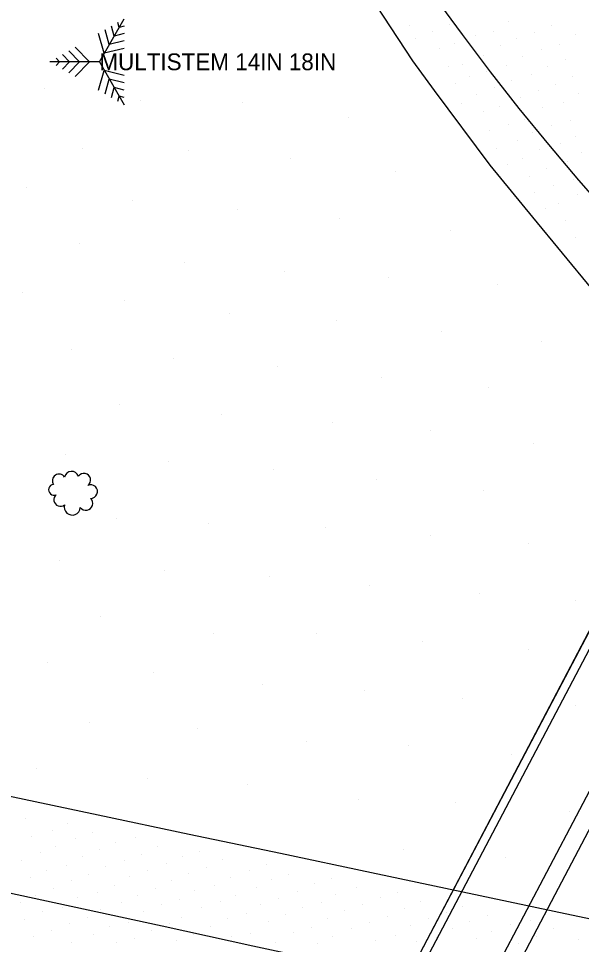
# Model space of a CAD drawing. Extents: x 1732346 to 1733076, y 467730 to 468633.
# Drawn here: x 1732679.1 to 1732739.5, y 468090 to 468189.3 of the extents above; entities that cross this region are included whole.
import ezdxf

# ---------------------------------------------------------------- set-up
doc = ezdxf.new("R2010")
doc.units = 0
for name, color, linetype in [('Default', 7, 'Continuous'), ('S_Bridge_BoxCulvert', 7, 'Continuous'), ('S_Ground_SpotElevation', 7, 'Continuous'), ('S_Railroad_Tracks', 7, 'Continuous'), ('S_Roadway_Edge_Pavement', 7, 'Continuous'), ('S_Roadway_Painted_Lines', 7, 'Continuous'), ('S_Text', 7, 'Continuous'), ('S_Trees_Bush', 7, 'Continuous'), ('S_Trees_Conifer_Pay', 7, 'Continuous'), ('TopoDOT Temp', 7, 'Continuous')]:
    doc.layers.add(name, color=color, linetype=linetype)

# ---------------------------------------------------------------- blocks, each defined once
blk = doc.blocks.new('POINT_DISPLAY')
at = {"layer": 'Default'}
blk.add_line((0, 0), (0, 0), dxfattribs=at)

msp = doc.modelspace()

# ---------------------------------------------------------------- linework, layer by layer
at = {"layer": 'S_Bridge_BoxCulvert'}
for p, q in [((1732639.349, 467931.595), (1732772.729, 468185.159)), ((1732639.356, 467931.621), (1732772.736, 468185.185)), ((1732640.157, 467931.201), (1732773.537, 468184.766)), ((1732646.436, 467927.898), (1732779.815, 468181.463))]:
    msp.add_line(p, q, dxfattribs=at)
at = {"layer": 'S_Railroad_Tracks'}
msp.add_lwpolyline([(1732680.786, 467989.136), (1732685.443, 467997.986), (1732690.1, 468006.835), (1732694.757, 468015.685), (1732699.414, 468024.534), (1732704.07, 468033.384), (1732708.727, 468042.233), (1732713.384, 468051.083), (1732718.041, 468059.932), (1732722.698, 468068.782), (1732727.355, 468077.631), (1732732.012, 468086.481), (1732736.669, 468095.33), (1732741.325, 468104.18), (1732745.982, 468113.029), (1732750.639, 468121.879), (1732755.296, 468130.728), (1732759.953, 468139.578), (1732764.61, 468148.427), (1732769.267, 468157.277), (1732773.924, 468166.126), (1732778.581, 468174.976), (1732783.237, 468183.825), (1732787.789, 468192.475)], dxfattribs=at)
at = {"layer": 'S_Roadway_Edge_Pavement'}
for points in [[(1732823.007, 468089.57), (1732821.659, 468091.736), (1732813.423, 468097.407), (1732807.383, 468101.566), (1732799.356, 468107.529), (1732792.806, 468112.395), (1732784.933, 468118.56), (1732778.351, 468123.714), (1732770.846, 468130.322), (1732766.796, 468133.889), (1732759.562, 468140.794), (1732752.667, 468147.374), (1732745.846, 468154.686), (1732740.622, 468160.287), (1732734.263, 468168.005), (1732729.679, 468173.568), (1732723.729, 468181.605), (1732721.39, 468184.764), (1732715.912, 468193.131)], [(1732677.839, 468105.951), (1732687.624, 468103.887), (1732697.408, 468101.822), (1732707.193, 468099.758), (1732716.978, 468097.693), (1732726.762, 468095.629), (1732736.547, 468093.564), (1732745.022, 468091.776), (1732754.805, 468089.704)]]:
    msp.add_lwpolyline(points, dxfattribs=at)
at = {"layer": 'S_Roadway_Painted_Lines'}
for points in [[(1732742.496, 468168.204), (1732739.21, 468171.965), (1732735.98, 468175.778), (1732732.819, 468179.654), (1732729.734, 468183.579), (1732726.724, 468187.592), (1732723.804, 468191.604)], [(1732674.928, 468096.211), (1732684.719, 468094.102), (1732694.509, 468091.966), (1732704.231, 468089.834), (1732713.923, 468087.737), (1732723.729, 468085.628), (1732733.386, 468083.606), (1732743.244, 468081.582), (1732753.103, 468079.541), (1732762.798, 468077.529), (1732772.584, 468075.483), (1732772.711, 468075.456), (1732782.31, 468073.445), (1732792.144, 468071.365), (1732801.882, 468069.322), (1732811.732, 468067.208), (1732821.504, 468065.09), (1732821.605, 468065.069), (1732831.424, 468062.914)]]:
    msp.add_lwpolyline(points, dxfattribs=at)
at = {"layer": 'S_Trees_Bush'}
for centre, radius, start, end in [((1732683.436, 468139.716), 0.716, 33.64054, 213.59091), ((1732684.789, 468139.951), 0.774, 19.72769, 168.00323), ((1732686.105, 468139.806), 0.714, 304.7168, 145.28321), ((1732682.892, 468138.748), 0.575, 95.18751, 295.46148), ((1732686.832, 468138.562), 0.731, 268.12197, 116.01721), ((1732683.584, 468137.682), 0.705, 129.15555, 309.41051), ((1732686.308, 468137.286), 0.74, 216.98087, 47.49649), ((1732684.858, 468136.897), 0.861, 163.74266, 356.27601)]:
    msp.add_arc(centre, radius, start, end, dxfattribs=at)
at = {"layer": 'S_Trees_Conifer_Pay'}
for p, q in [((1732687.761, 468184.664), (1732690.424, 468189.275)), ((1732689.356, 468187.428), (1732689.055, 468188.484)), ((1732689.89, 468188.352), (1732689.74, 468188.881)), ((1732690.424, 468188.484), (1732689.89, 468188.352)), ((1732688.293, 468185.587), (1732687.686, 468187.693)), ((1732688.827, 468186.508), (1732688.37, 468188.087)), ((1732690.424, 468187.693), (1732689.356, 468187.428)), ((1732690.424, 468186.905), (1732688.827, 468186.508)), ((1732684.566, 468184.664), (1732683.806, 468185.452)), ((1732685.632, 468184.664), (1732684.491, 468185.849)), ((1732686.695, 468184.664), (1732685.175, 468186.246)), ((1732690.424, 468186.111), (1732688.293, 468185.587)), ((1732687.761, 468184.664), (1732682.437, 468184.664)), ((1732683.5, 468184.664), (1732683.122, 468185.058)), ((1732683.122, 468184.27), (1732683.5, 468184.664)), ((1732683.806, 468183.873), (1732684.566, 468184.664)), ((1732684.491, 468183.476), (1732685.632, 468184.664)), ((1732685.175, 468183.082), (1732686.695, 468184.664)), ((1732687.761, 468184.664), (1732690.424, 468180.053)), ((1732687.686, 468181.635), (1732688.293, 468183.741)), ((1732690.424, 468183.214), (1732688.293, 468183.741)), ((1732688.37, 468181.238), (1732688.827, 468182.818)), ((1732690.424, 468182.423), (1732688.827, 468182.818)), ((1732689.055, 468180.841), (1732689.356, 468181.897)), ((1732690.424, 468181.635), (1732689.356, 468181.897)), ((1732689.74, 468180.447), (1732689.89, 468180.976)), ((1732690.424, 468180.841), (1732689.89, 468180.976))]:
    msp.add_line(p, q, dxfattribs=at)
at = {"layer": 'TopoDOT Temp'}
msp.add_line((1732736.669, 468095.33), (1732736.669, 468095.33), dxfattribs=at)

# ---------------------------------------------------------------- block references
at = {"layer": 'S_Ground_SpotElevation'}
for p in [(1732721.005, 468188.524), (1732725.336, 468188.641), (1732731.668, 468189.027), (1732736.313, 468188.604), (1732687.655, 468187.573), (1732723.483, 468187.889), (1732728.143, 468187.444), (1732730.075, 468187.947), (1732734.5, 468187.831), (1732738.874, 468187.545), (1732721.705, 468187.134), (1732725.877, 468186.679), (1732732.555, 468187.164), (1732737.111, 468186.486), (1732698.99, 468185.516), (1732724.248, 468186.076), (1732730.797, 468186.365), (1732735.209, 468185.954), (1732709.393, 468184.816), (1732729.006, 468185.38), (1732733.2, 468185.258), (1732737.769, 468184.901), (1732725.231, 468184.112), (1732726.696, 468184.41), (1732729.331, 468183.667), (1732731.401, 468184.287), (1732735.863, 468184.212), (1732727.428, 468183.053), (1732731.948, 468182.669), (1732734.178, 468183.267), (1732738.503, 468183.062), (1732681.861, 468181.849), (1732725.95, 468182.288), (1732730.162, 468181.944), (1732734.849, 468181.557), (1732736.715, 468182.253), (1732692.18, 468180.569), (1732728.278, 468181.135), (1732732.975, 468180.829), (1732739.144, 468181.242), (1732703.099, 468180.307), (1732726.652, 468180.199), (1732730.704, 468179.842), (1732735.325, 468179.768), (1732737.557, 468180.261), (1732714.539, 468178.694), (1732729.03, 468179.329), (1732733.375, 468178.505), (1732731.707, 468177.891), (1732736.28, 468177.881), (1732738.315, 468178.364), (1732729.599, 468177.317), (1732734.278, 468177.083), (1732738.9, 468176.627), (1732732.659, 468176.275), (1732737.198, 468175.877), (1732685.98, 468175.337), (1732697.342, 468175.12), (1732730.327, 468175.354), (1732735.036, 468175.311), (1732739.458, 468174.884), (1732708.298, 468174.241), (1732731.59, 468173.635), (1732733.118, 468174.294), (1732737.947, 468173.979), (1732719.558, 468172.905), (1732735.766, 468173.224), (1732733.921, 468172.339), (1732738.583, 468172.034), (1732679.976, 468171.195), (1732734.482, 468170.621), (1732736.532, 468171.417), (1732691.358, 468169.833), (1732739.099, 468170.44), (1732702.593, 468168.821), (1732735.595, 468168.885), (1732737.033, 468169.422), (1732713.566, 468167.814), (1732737.783, 468167.637), (1732725.387, 468166.554), (1732738.89, 468165.866), (1732685.677, 468165.208), (1732696.947, 468163.119), (1732707.619, 468162.212), (1732718.734, 468161.474), (1732730.485, 468160.792), (1732679.559, 468159.953), (1732690.487, 468159.041), (1732701.697, 468157.65), (1732713.214, 468156.862), (1732724.449, 468155.732), (1732684.759, 468153.795), (1732735.19, 468154.608), (1732695.671, 468152.857), (1732706.851, 468151.934), (1732718.061, 468150.804), (1732729.562, 468149.681), (1732689.939, 468147.951), (1732700.853, 468146.779), (1732712.827, 468145.953), (1732723.255, 468145.137), (1732734.301, 468143.725), (1732684.157, 468142.581), (1732695.2, 468141.83), (1732706.46, 468140.902), (1732717.533, 468139.86), (1732729.024, 468138.647), (1732689.584, 468135.629), (1732699.515, 468135.124), (1732711.976, 468134.71), (1732723.306, 468133.862), (1732733.758, 468132.99), (1732683.533, 468131.138), (1732694.723, 468130.129), (1732705.979, 468129.461), (1732716.77, 468128.475), (1732728.558, 468127.669), (1732738.816, 468126.837), (1732687.925, 468125.2), (1732700.044, 468123.361), (1732711.035, 468123.369), (1732722.452, 468122.496), (1732733.767, 468121.624), (1732682.154, 468120.172), (1732693.605, 468119.102), (1732705.238, 468117.895), (1732716.23, 468117.203), (1732726.721, 468116.378), (1732738.823, 468115.596), (1732686.749, 468113.754), (1732698.272, 468113.136), (1732709.983, 468111.7), (1732720.948, 468111.267), (1732731.984, 468110.334), (1732681.013, 468108.882), (1732692.96, 468107.793), (1732703.623, 468107.116), (1732715.556, 468105.503), (1732725.973, 468105.18), (1732738.155, 468104.216), (1732679.879, 468103.498), (1732682.684, 468102.236), (1732684.375, 468102.995), (1732680.431, 468101.584), (1732685.148, 468101.31), (1732687.075, 468101.974), (1732691.622, 468101.487), (1732683.093, 468100.509), (1732687.759, 468100.188), (1732689.471, 468100.961), (1732694.015, 468100.482), (1732720.426, 468100.111), (1732681.452, 468099.798), (1732686.003, 468099.361), (1732692.248, 468099.634), (1732696.668, 468099.465), (1732698.481, 468100.002), (1732700.964, 468099.079), (1732731.354, 468099.296), (1732679.419, 468099.026), (1732684.194, 468098.46), (1732688.401, 468098.351), (1732690.44, 468099.019), (1732694.93, 468098.63), (1732699.219, 468098.272), (1732705.722, 468098.521), (1732680.391, 468097.173), (1732682.086, 468097.905), (1732686.612, 468097.481), (1732691.031, 468097.24), (1732692.979, 468097.941), (1732697.282, 468097.625), (1732701.875, 468097.207), (1732703.831, 468097.894), (1732708.095, 468097.519), (1732684.727, 468096.87), (1732689.37, 468096.351), (1732695.508, 468096.802), (1732700.097, 468096.346), (1732704.57, 468096.061), (1732706.204, 468096.904), (1732710.816, 468096.5), (1732712.638, 468097.021), (1732715.332, 468096.07), (1732680.942, 468095.188), (1732682.813, 468096.001), (1732687.513, 468095.564), (1732691.857, 468095.28), (1732693.777, 468095.964), (1732698.012, 468095.763), (1732702.373, 468095.243), (1732709.03, 468095.65), (1732713.149, 468095.387), (1732719.742, 468095.566), (1732679.293, 468094.452), (1732685.365, 468095.012), (1732690.091, 468094.436), (1732694.48, 468094.218), (1732696.388, 468094.839), (1732700.757, 468094.572), (1732705.075, 468094.25), (1732707.027, 468094.922), (1732711.628, 468094.494), (1732715.948, 468094.283), (1732717.909, 468095.002), (1732722.216, 468094.635), (1732726.673, 468094.078), (1732681.71, 468093.465), (1732683.795, 468093.98), (1732687.88, 468093.75), (1732692.518, 468093.499), (1732698.719, 468093.907), (1732703.545, 468093.295), (1732707.728, 468093.16), (1732709.584, 468093.911), (1732714.022, 468093.576), (1732720.478, 468093.855), (1732725.039, 468093.379), (1732729.459, 468093.108), (1732679.714, 468092.673), (1732684.513, 468092.175), (1732686.436, 468092.865), (1732690.888, 468092.385), (1732695.316, 468092.189), (1732696.607, 468092.897), (1732701.498, 468092.752), (1732705.911, 468092.429), (1732712.279, 468092.762), (1732716.727, 468092.279), (1732718.708, 468093.006), (1732723.114, 468092.721), (1732727.45, 468092.401), (1732731.912, 468092.105), (1732733.977, 468092.529), (1732682.635, 468091.522), (1732688.887, 468091.942), (1732693.371, 468091.457), (1732699.678, 468091.941), (1732703.934, 468091.179), (1732708.606, 468091.216), (1732710.478, 468091.835), (1732714.857, 468091.682), (1732721.172, 468092.05), (1732725.634, 468091.706), (1732729.873, 468091.356), (1732736.497, 468091.651), (1732680.735, 468090.864), (1732684.773, 468090.219), (1732687.126, 468091.053), (1732689.567, 468090.14), (1732691.528, 468090.591), (1732696.043, 468090.403), (1732697.813, 468091.049), (1732701.965, 468090.802), (1732706.68, 468090.155), (1732711.128, 468090.094), (1732712.821, 468090.873), (1732717.35, 468090.442), (1732719.502, 468090.964), (1732721.822, 468090.245), (1732723.94, 468090.752), (1732728.183, 468090.625), (1732732.722, 468090.104), (1732734.703, 468090.796), (1732739.131, 468090.481)]:
    msp.add_blockref('POINT_DISPLAY', p, dxfattribs=at)

# ---------------------------------------------------------------- texts
at = {"layer": 'S_Text'}
msp.add_text('MULTISTEM 14IN 18IN', height=1.8, dxfattribs=at).set_placement((1732687.761, 468183.764))

doc.saveas('drawing.dxf')
